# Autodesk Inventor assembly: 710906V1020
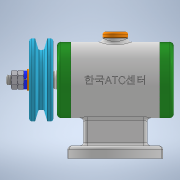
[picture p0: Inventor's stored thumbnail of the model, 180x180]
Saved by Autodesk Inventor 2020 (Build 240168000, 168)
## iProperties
Created: 2021-09
Part Number: 710906V1020
Document SubType Name: Assembly
Designer: Administrator
Author: Administrator
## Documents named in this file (14)
- C:\Users\Administrator\Desktop\710906V1020\710906V1020.iam
- C:\Users\Administrator\Desktop\710906V1020\본체.ipt
- C:\Users\Administrator\Desktop\710906V1020\축.ipt
- C:\Users\Administrator\Desktop\710906V1020\베어링 15x32x9.ipt
- C:\Users\Administrator\Desktop\710906V1020\뒤커버.ipt
- C:\Users\Administrator\Desktop\710906V1020\앞커버.ipt
- C:\Users\Administrator\Desktop\710906V1020\오일 실 15x25x7.ipt
- C:\Users\Administrator\Desktop\710906V1020\캡.ipt
- C:\Users\Administrator\Desktop\710906V1020\키 3x3.ipt
- C:\Users\Administrator\Desktop\710906V1020\볼트 M4x12.ipt
- C:\Users\Administrator\Desktop\710906V1020\V벨트풀리.ipt
- C:\Users\Administrator\Desktop\710906V1020\와셔 8x17.ipt
- C:\Users\Administrator\Desktop\710906V1020\스프링와셔 8.ipt
- C:\Users\Administrator\Desktop\710906V1020\너트 M8.ipt
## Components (1 placed, 1 different names)
1. V벨트풀리:1
